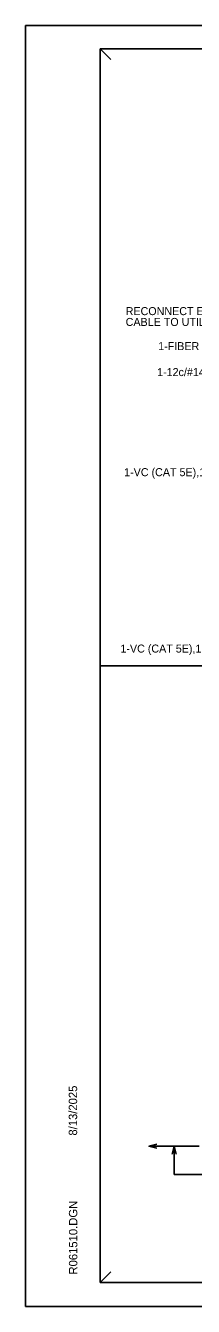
# Model space of a CAD drawing. Extents: x 635746 to 638310, y 744089 to 745312.
# Drawn here: x 636518 to 636602, y 744089 to 744729 of the extents above; entities that cross this region are included whole.
import ezdxf

# ---------------------------------------------------------------- set-up
doc = ezdxf.new("R2010")
doc.units = 0
for name, color, linetype in [('R_Border', 7, 'Continuous'), ('R_Grid', 7, 'Continuous'), ('R_No Plot', 7, 'Continuous'), ('T_Drafting', 7, 'Continuous'), ('T_Notes', 7, 'Continuous')]:
    doc.layers.add(name, color=color, linetype=linetype)

msp = doc.modelspace()

# ---------------------------------------------------------------- linework, layer by layer
at = {"layer": 'R_Border'}
for p, q in [((636555.15, 744717.46), (637503.69, 744717.46)), ((636555.15, 744101.08), (636555.15, 744717.46)), ((636555.15, 744101.08), (636555.15, 744101.08)), ((637503.69, 744101.08), (636555.15, 744101.08))]:
    msp.add_line(p, q, dxfattribs=at)
at = {"layer": 'R_Grid'}
for p, q in [((636555.15, 744717.46), (636560.46, 744712.15)), ((636555.15, 744409.27), (637503.69, 744409.27)), ((636555.15, 744101.08), (636560.46, 744106.38))]:
    msp.add_line(p, q, dxfattribs=at)
at = {"layer": 'R_No Plot'}
for p, q in [((636517.95, 744729.14), (637517.95, 744729.14)), ((636517.95, 744089.14), (637517.95, 744089.14))]:
    msp.add_line(p, q, dxfattribs=at)
msp.add_lwpolyline([(636517.93, 744729.14), (637517.95, 744729.14), (637517.95, 744089.13), (636517.93, 744089.13)], close=True, dxfattribs=at)
at = {"layer": 'T_Drafting'}
msp.add_line((636604.47, 744169.17), (636579.47, 744169.17), dxfattribs=at)
at = {"layer": 'T_Notes'}
for p, q in [((636591.97, 744169.17), (636591.97, 744155.01)), ((636591.97, 744155.01), (636634.48, 744155.01))]:
    msp.add_line(p, q, dxfattribs=at)
for points in [[(636583.47, 744168.17), (636579.47, 744169.17), (636583.47, 744170.17)], [(636590.97, 744165.17), (636591.97, 744169.17), (636592.97, 744165.17)]]:
    msp.add_lwpolyline(points, dxfattribs=at)

# ---------------------------------------------------------------- texts
at = {"layer": 'R_Border'}
for s, p in [('8/13/2025', (636543.63, 744174.47)), ('R061510.DGN', (636543.73, 744105.05))]:
    msp.add_text(s, height=4.2, rotation=90, dxfattribs=at).set_placement(p)
at = {"layer": 'T_Notes'}
for s, p in [('RECONNECT EXISTING FIBER OPTIC', (636567.85, 744584.47)), ('CABLE TO UTILITY POLE', (636567.85, 744579.06)), ('1-FIBER OPTIC CABLE (EXIST.)', (636584.07, 744566.97)), ('1-12c/#14,1-VC (CAT 5E),1-3c/#14,', (636583.54, 744554.01)), ('1-VC (CAT 5E),1-3c/#14', (636567.08, 744503.99)), ('1-VC (CAT 5E),1-3c/#14', (636565.22, 744415.84))]:
    msp.add_text(s, height=4, dxfattribs=at).set_placement(p)

doc.saveas('drawing.dxf')
